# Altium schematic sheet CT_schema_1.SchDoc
size 397 x 272 mm
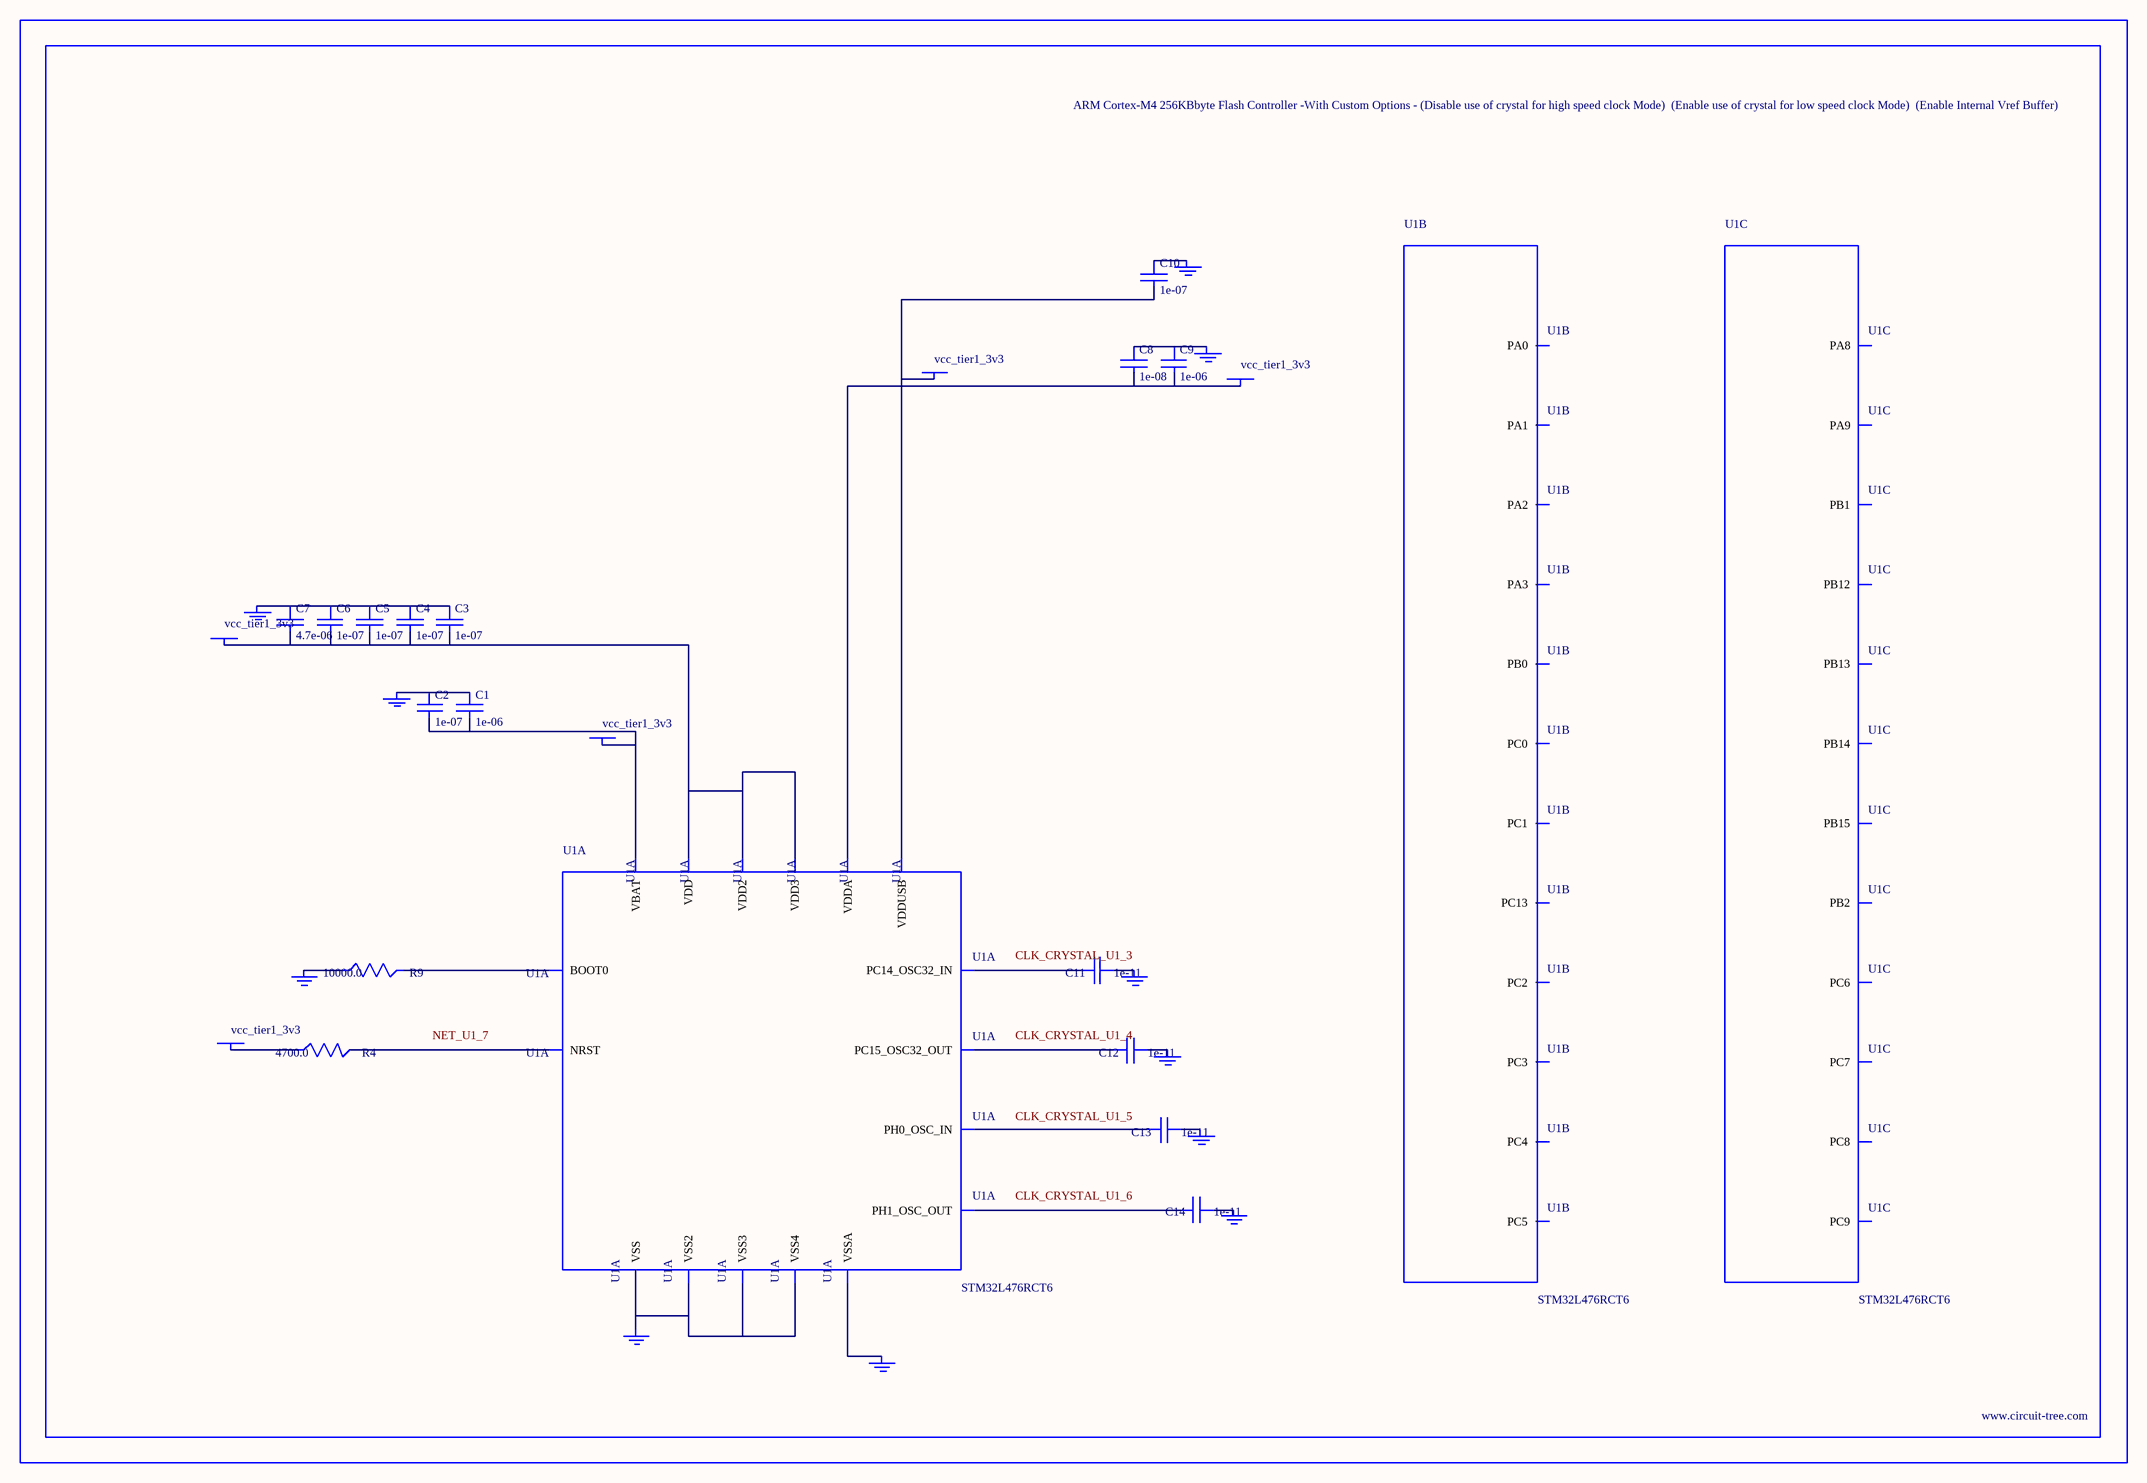
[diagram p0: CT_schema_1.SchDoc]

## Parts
BORDER0  (no value)
C1  1e-06  [C0603]
C2  1e-07  [C0603]
C3  1e-07  [C0603]
C4  1e-07  [C0603]
C5  1e-07  [C0603]
C6  1e-07  [C0603]
C7  4.7e-06  [C0603]
C8  1e-08  [C0603]
C9  1e-06  [C0603]
C10  1e-07  [C0603]
C11  1e-11  [C0402]
C12  1e-11  [C0402]
C13  1e-11  [C0402]
C14  1e-11  [C0402]
GND_INSTANCE_0_0  (no value)
GND_INSTANCE_0_1  (no value)
GND_INSTANCE_0_2  (no value)
GND_INSTANCE_0_3  (no value)
GND_INSTANCE_0_4  (no value)
GND_INSTANCE_0_5  (no value)
GND_INSTANCE_0_6  (no value)
GND_INSTANCE_0_7  (no value)
GND_INSTANCE_0_8  (no value)
GND_INSTANCE_0_9  (no value)
GND_INSTANCE_0_10  (no value)
POWER_INSTANCE_0_0  vcc_tier1_3v3
POWER_INSTANCE_0_1  vcc_tier1_3v3
POWER_INSTANCE_0_2  vcc_tier1_3v3
POWER_INSTANCE_0_3  vcc_tier1_3v3
POWER_INSTANCE_0_4  vcc_tier1_3v3
R4  4700.0  [R0603]
R9  10000.0  [R0603]
U1  STM32L476RCT6  [LQFP64]  (parts A,B,C of 6)

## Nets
NetC1_1: C1.1 C2.1 GND_INSTANCE_0_0.0(GND)
NetC1_2: C1.2 C2.2 POWER_INSTANCE_0_0.0(PWR) U1.1(VBAT)
NetC3_1: C3.1 C4.1 C5.1 C6.1 C7.1 GND_INSTANCE_0_7.0(GND)
NetC3_2: C3.2 C4.2 C5.2 C6.2 C7.2 POWER_INSTANCE_0_2.0(PWR) U1.19(VDD) U1.32(VDD2) U1.64(VDD3)
NetC8_1: C8.1 C9.1 GND_INSTANCE_0_6.0(GND)
NetC8_2: C8.2 C9.2 POWER_INSTANCE_0_1.0(PWR) U1.13(VDDA)
NetC10_1: C10.1 GND_INSTANCE_0_8.0(GND)
NetC10_2: C10.2 POWER_INSTANCE_0_3.0(PWR) U1.48(VDDUSB)
NetC11_1: C11.1 GND_INSTANCE_0_1.0(GND)
NetC11_2: C11.2 U1.3(PC14_OSC32_IN)
NetC12_1: C12.1 GND_INSTANCE_0_2.0(GND)
NetC12_2: C12.2 U1.4(PC15_OSC32_OUT)
NetC13_1: C13.1 GND_INSTANCE_0_3.0(GND)
NetC13_2: C13.2 U1.5(PH0_OSC_IN)
NetC14_1: C14.1 GND_INSTANCE_0_4.0(GND)
NetC14_2: C14.2 U1.6(PH1_OSC_OUT)
NetGND_INSTANCE_0_5_0: GND_INSTANCE_0_5.0(GND) U1.12(VSSA)
NetGND_INSTANCE_0_9_0: GND_INSTANCE_0_9.0(GND) R9.1
NetGND_INSTANCE_0_10_0: GND_INSTANCE_0_10.0(GND) U1.18(VSS) U1.31(VSS2) U1.47(VSS3) U1.63(VSS4)
NetPOWER_INSTANCE_0_4_0: POWER_INSTANCE_0_4.0(PWR) R4.1
NetR4_2: R4.2 U1.7(NRST)
NetR9_2: R9.2 U1.60(BOOT0)

Not connected (* = marked no-connect by the designer): U1 2(PC13) 8(PC0) 9(PC1) 10(PC2) 11(PC3) 14(PA0) 15(PA1) 16(PA2) 17(PA3) 24(PC4) 25(PC5) 26(PB0) 27(PB1) 28(PB2) 33(PB12) 34(PB13) 35(PB14) 36(PB15) 37(PC6) 38(PC7) 39(PC8) 40(PC9) 41(PA8) 42(PA9)

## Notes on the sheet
- Labels drawn without touching a wire or pin: CLK_CRYSTAL_U1_3, CLK_CRYSTAL_U1_4, CLK_CRYSTAL_U1_5, CLK_CRYSTAL_U1_6, NET_U1_7

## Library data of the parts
BORDER0 = BORDER_PAGE0
C1 C9 = C0603C105K3RACTU
C2-C6 C10 = 06035C104K4Z2A
C7 = GRM188R6YA475KE15D
C8 = 06035C103K4Z2A
C11-C14 = C0402C100K3GACTU
GND_INSTANCE_0_0-GND_INSTANCE_0_10 = GND
POWER_INSTANCE_0_0-POWER_INSTANCE_0_4 = PWR
R4 = RC0603JR-074K7L
R9 = RC0603JR-0710KL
